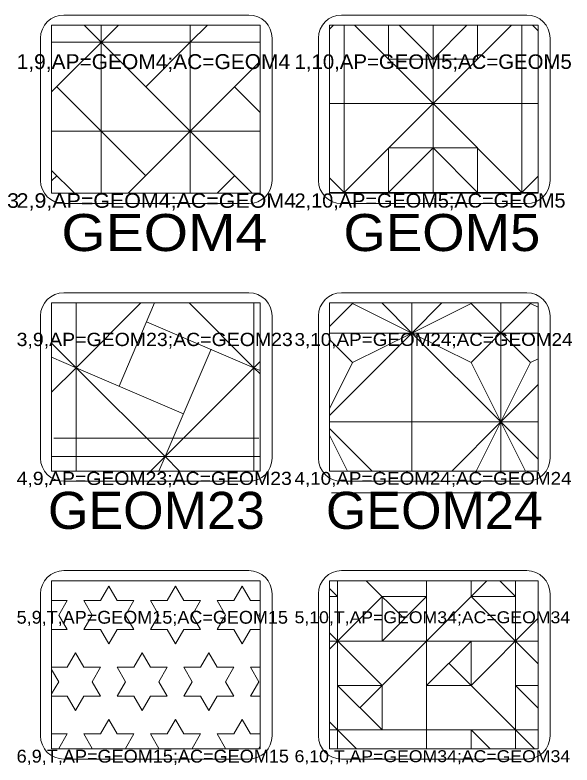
# Model space of a CAD drawing. Extents: x 95935 to 95946.4, y 95971.2 to 95974.7.
# Drawn here: x 95939.831 to 95941.033, y 95973.112 to 95974.732 of the extents above; entities that cross this region are included whole.
import ezdxf
from ezdxf.enums import TextEntityAlignment as Align

# ---------------------------------------------------------------- set-up
doc = ezdxf.new("R2010")
doc.units = 0
doc.header["$LTSCALE"] = 0.032
for name, color, linetype, lineweight in [('1', 7, 'Continuous', 13), ('2', 7, 'Continuous', 13), ('25', 7, 'Continuous', 13), ('6', 7, 'Continuous', 13), ('63', 7, 'Continuous', 13)]:
    doc.layers.add(name, color=color, linetype=linetype, lineweight=lineweight)
doc.layers.add('20', color=7, linetype='Continuous')

msp = doc.modelspace()

# ---------------------------------------------------------------- linework, layer by layer
at = {"layer": '1'}
for p, q in [((95939.9357, 95974.7318), (95940.3357, 95974.7318)), ((95940.5357, 95974.7318), (95940.9357, 95974.7318)), ((95939.8857, 95974.3747), (95939.8857, 95974.6818)), ((95940.3857, 95974.6818), (95940.3857, 95974.3747)), ((95940.4857, 95974.3747), (95940.4857, 95974.6818)), ((95940.9857, 95974.6818), (95940.9857, 95974.3747)), ((95940.3357, 95974.3247), (95939.9357, 95974.3247)), ((95940.9357, 95974.3247), (95940.5357, 95974.3247)), ((95939.9357, 95974.1318), (95940.3357, 95974.1318)), ((95940.5357, 95974.1318), (95940.9357, 95974.1318)), ((95939.8857, 95973.7747), (95939.8857, 95974.0818)), ((95940.3857, 95974.0818), (95940.3857, 95973.7747)), ((95940.4857, 95973.7747), (95940.4857, 95974.0818)), ((95940.9857, 95974.0818), (95940.9857, 95973.7747)), ((95940.3357, 95973.7247), (95939.9357, 95973.7247)), ((95940.9357, 95973.7247), (95940.5357, 95973.7247)), ((95939.9357, 95973.5318), (95940.3357, 95973.5318)), ((95940.5357, 95973.5318), (95940.9357, 95973.5318)), ((95939.8857, 95973.1747), (95939.8857, 95973.4818)), ((95940.3857, 95973.4818), (95940.3857, 95973.1747)), ((95940.4857, 95973.1747), (95940.4857, 95973.4818)), ((95940.9857, 95973.4818), (95940.9857, 95973.1747)), ((95940.3357, 95973.1247), (95939.9357, 95973.1247)), ((95940.9357, 95973.1247), (95940.5357, 95973.1247))]:
    msp.add_line(p, q, dxfattribs=at)
for centre, start, end in [((95939.9357, 95974.6818), 90, 180), ((95940.3357, 95974.6818), 0, 90), ((95940.5357, 95974.6818), 90, 180), ((95940.9357, 95974.6818), 0, 90), ((95939.9357, 95974.3747), 180, 270), ((95940.3357, 95974.3747), 270, 0), ((95940.5357, 95974.3747), 180, 270), ((95940.9357, 95974.3747), 270, 0), ((95939.9357, 95974.0818), 90, 180), ((95940.3357, 95974.0818), 0, 90), ((95940.5357, 95974.0818), 90, 180), ((95940.9357, 95974.0818), 0, 90), ((95939.9357, 95973.7747), 180, 270), ((95940.3357, 95973.7747), 270, 0), ((95940.5357, 95973.7747), 180, 270), ((95940.9357, 95973.7747), 270, 0), ((95939.9357, 95973.4818), 90, 180), ((95940.3357, 95973.4818), 0, 90), ((95940.5357, 95973.4818), 90, 180), ((95940.9357, 95973.4818), 0, 90), ((95939.9357, 95973.1747), 180, 270), ((95940.3357, 95973.1747), 270, 0), ((95940.5357, 95973.1747), 180, 270), ((95940.9357, 95973.1747), 270, 0)]:
    msp.add_arc(centre, 0.05, start, end, dxfattribs=at)
at = {"layer": '2'}
for points in [[(95940.3601, 95974.7099), (95939.9097, 95974.7099), (95939.9097, 95974.3468), (95940.3601, 95974.3468)], [(95940.9601, 95974.7099), (95940.5097, 95974.7099), (95940.5097, 95974.3468), (95940.9601, 95974.3468)], [(95940.3601, 95974.1099), (95939.9097, 95974.1099), (95939.9097, 95973.7468), (95940.3601, 95973.7468)], [(95940.9601, 95974.1099), (95940.5097, 95974.1099), (95940.5097, 95973.7468), (95940.9601, 95973.7468)], [(95940.3601, 95973.5099), (95939.9097, 95973.5099), (95939.9097, 95973.1468), (95940.3601, 95973.1468)], [(95940.9601, 95973.5099), (95940.5097, 95973.5099), (95940.5097, 95973.1468), (95940.9601, 95973.1468)]]:
    msp.add_lwpolyline(points, close=True, dxfattribs=at)
at = {"layer": '25'}
for p, q in [((95940.3569, 95973.8178), (95939.9141, 95973.8178)), ((95940.9569, 95973.6997), (95940.5141, 95973.6997))]:
    msp.add_line(p, q, dxfattribs=at)
at = {"layer": '6'}
for p, q in [((95939.9097, 95974.5657), (95940.0539, 95974.7099)), ((95940.2088, 95974.4808), (95939.9797, 95974.7099)), ((95940.0168, 95974.7099), (95940.0168, 95974.3468)), ((95940.2088, 95974.7099), (95940.2088, 95974.3468)), ((95940.2459, 95974.7099), (95940.2088, 95974.6728)), ((95940.5183, 95974.7099), (95940.5097, 95974.7013)), ((95940.541, 95974.7099), (95940.541, 95974.3468)), ((95940.733, 95974.5406), (95940.5637, 95974.7099)), ((95940.637, 95974.7099), (95940.637, 95974.6366)), ((95940.733, 95974.6366), (95940.6597, 95974.7099)), ((95940.733, 95974.7099), (95940.733, 95974.3468)), ((95940.9023, 95974.7099), (95940.733, 95974.5406)), ((95940.733, 95974.6366), (95940.8063, 95974.7099)), ((95940.829, 95974.7099), (95940.829, 95974.6366)), ((95940.925, 95974.7099), (95940.925, 95974.3468)), ((95940.9601, 95974.6975), (95940.9477, 95974.7099)), ((95939.9097, 95974.6728), (95940.3601, 95974.6728)), ((95940.1128, 95974.5768), (95940.2088, 95974.6728)), ((95940.2088, 95974.4808), (95940.3601, 95974.6321)), ((95940.637, 95974.6366), (95940.733, 95974.6366)), ((95940.829, 95974.6366), (95940.733, 95974.6366)), ((95939.9208, 95974.5768), (95940.0168, 95974.4808)), ((95940.3048, 95974.5768), (95940.3601, 95974.5215)), ((95940.5097, 95974.5406), (95940.9601, 95974.5406)), ((95940.541, 95974.3486), (95940.733, 95974.5406)), ((95940.733, 95974.5406), (95940.925, 95974.3486)), ((95939.9097, 95974.4808), (95940.3601, 95974.4808)), ((95940.1128, 95974.3848), (95940.0168, 95974.4808)), ((95940.0748, 95974.3468), (95940.2088, 95974.4808)), ((95940.3428, 95974.3468), (95940.2088, 95974.4808)), ((95939.9588, 95974.3468), (95939.9097, 95974.3959)), ((95939.9208, 95974.3848), (95939.9097, 95974.3737)), ((95940.3048, 95974.3848), (95940.2668, 95974.3468)), ((95940.5097, 95974.3799), (95940.541, 95974.3486)), ((95940.925, 95974.3486), (95940.9601, 95974.3837)), ((95940.5097, 95974.3486), (95940.9601, 95974.3486)), ((95940.541, 95974.3486), (95940.5392, 95974.3468)), ((95940.5428, 95974.3468), (95940.541, 95974.3486)), ((95940.637, 95974.3486), (95940.637, 95974.3468)), ((95940.6388, 95974.3468), (95940.637, 95974.3486)), ((95940.8272, 95974.3468), (95940.829, 95974.3486)), ((95940.829, 95974.3486), (95940.829, 95974.3468)), ((95940.925, 95974.3486), (95940.9232, 95974.3468)), ((95940.9268, 95974.3468), (95940.925, 95974.3486)), ((95939.9625, 95974.1099), (95939.9625, 95973.7468)), ((95940.1023, 95974.1099), (95939.9625, 95973.9701)), ((95940.1321, 95974.1099), (95940.0552, 95973.9304)), ((95940.3465, 95973.9701), (95940.2067, 95974.1099)), ((95940.3465, 95974.1099), (95940.3465, 95973.7468)), ((95940.5595, 95974.109), (95940.5097, 95974.0592)), ((95940.5595, 95974.109), (95940.5591, 95974.1099)), ((95940.6875, 95974.1099), (95940.6875, 95973.7468)), ((95940.7524, 95974.1099), (95940.6875, 95974.045)), ((95940.816, 95974.1099), (95940.8155, 95974.109)), ((95940.8155, 95974.109), (95940.9435, 95973.981)), ((95940.9435, 95974.109), (95940.8155, 95973.981)), ((95940.8795, 95974.1099), (95940.8795, 95973.7468)), ((95940.3465, 95973.9701), (95940.1148, 95974.0694)), ((95940.5097, 95974.045), (95940.9601, 95974.045)), ((95940.6875, 95974.045), (95940.8795, 95973.853)), ((95940.5097, 95974.0308), (95940.5595, 95973.981)), ((95940.1545, 95973.7781), (95940.2538, 95974.0098)), ((95939.9625, 95973.9701), (95939.9097, 95973.9927)), ((95940.5097, 95973.8814), (95940.5595, 95973.981)), ((95940.9435, 95973.981), (95940.9601, 95973.9893)), ((95939.9625, 95973.9701), (95940.1942, 95973.8708)), ((95940.3465, 95973.9701), (95940.3601, 95973.9643)), ((95940.8795, 95973.853), (95940.9601, 95973.9336)), ((95940.5097, 95973.853), (95940.9601, 95973.853)), ((95940.8795, 95973.853), (95940.7733, 95973.7468)), ((95940.9326, 95973.7468), (95940.8795, 95973.853)), ((95940.6017, 95973.7468), (95940.5097, 95973.8388)), ((95940.5486, 95973.7468), (95940.5097, 95973.8246)), ((95939.9097, 95973.7781), (95940.3601, 95973.7781)), ((95940.1545, 95973.7781), (95940.1232, 95973.7468)), ((95940.5271, 95973.5099), (95940.5271, 95973.1468)), ((95940.589, 95973.5099), (95940.6711, 95973.4278)), ((95940.7191, 95973.5099), (95940.7191, 95973.1468)), ((95940.7191, 95973.3798), (95940.8492, 95973.5099)), ((95940.8151, 95973.5099), (95940.8151, 95973.4758)), ((95940.9111, 95973.4758), (95940.877, 95973.5099)), ((95940.9111, 95973.5099), (95940.9111, 95973.1468)), ((95940.0329, 95973.4981), (95940.0149, 95973.467)), ((95940.0329, 95973.4981), (95940.0509, 95973.467)), ((95940.1769, 95973.4981), (95940.1589, 95973.467)), ((95940.1769, 95973.4981), (95940.1949, 95973.467)), ((95940.3209, 95973.4981), (95940.3029, 95973.467)), ((95940.3209, 95973.4981), (95940.3389, 95973.467)), ((95940.6231, 95973.4758), (95940.5097, 95973.3624)), ((95940.8151, 95973.4758), (95940.9111, 95973.4758)), ((95940.8151, 95973.4758), (95940.9601, 95973.3308)), ((95939.9429, 95973.467), (95939.9097, 95973.467)), ((95939.9429, 95973.467), (95939.9249, 95973.4358)), ((95939.9789, 95973.467), (95940.0149, 95973.467)), ((95939.9789, 95973.467), (95939.9969, 95973.4358)), ((95940.0869, 95973.467), (95940.0509, 95973.467)), ((95940.0869, 95973.467), (95940.0689, 95973.4358)), ((95940.1229, 95973.467), (95940.1589, 95973.467)), ((95940.1229, 95973.467), (95940.1409, 95973.4358)), ((95940.2309, 95973.467), (95940.1949, 95973.467)), ((95940.2309, 95973.467), (95940.2129, 95973.4358)), ((95940.2669, 95973.467), (95940.3029, 95973.467)), ((95940.2669, 95973.467), (95940.2849, 95973.4358)), ((95940.3601, 95973.467), (95940.3389, 95973.467)), ((95940.3601, 95973.4413), (95940.3569, 95973.4358)), ((95939.9429, 95973.4046), (95939.9249, 95973.4358)), ((95939.9789, 95973.4046), (95939.9969, 95973.4358)), ((95940.0869, 95973.4046), (95940.0689, 95973.4358)), ((95940.1229, 95973.4046), (95940.1409, 95973.4358)), ((95940.2309, 95973.4046), (95940.2129, 95973.4358)), ((95940.2669, 95973.4046), (95940.2849, 95973.4358)), ((95940.3601, 95973.4303), (95940.3569, 95973.4358)), ((95940.9601, 95973.4288), (95940.8151, 95973.2838)), ((95939.9429, 95973.4046), (95939.9097, 95973.4046)), ((95939.9789, 95973.4046), (95940.0149, 95973.4046)), ((95940.0329, 95973.3734), (95940.0149, 95973.4046)), ((95940.0329, 95973.3734), (95940.0509, 95973.4046)), ((95940.0869, 95973.4046), (95940.0509, 95973.4046)), ((95940.1229, 95973.4046), (95940.1589, 95973.4046)), ((95940.1769, 95973.3734), (95940.1589, 95973.4046)), ((95940.1769, 95973.3734), (95940.1949, 95973.4046)), ((95940.2309, 95973.4046), (95940.1949, 95973.4046)), ((95940.2669, 95973.4046), (95940.3029, 95973.4046)), ((95940.3209, 95973.3734), (95940.3029, 95973.4046)), ((95940.3209, 95973.3734), (95940.3389, 95973.4046)), ((95940.3601, 95973.4046), (95940.3389, 95973.4046)), ((95940.5097, 95973.3972), (95940.6231, 95973.2838)), ((95940.5097, 95973.3798), (95940.9601, 95973.3798)), ((95940.7191, 95973.3798), (95940.5751, 95973.2358)), ((95939.9609, 95973.3541), (95939.9429, 95973.323)), ((95939.9609, 95973.3541), (95939.9789, 95973.323)), ((95940.1049, 95973.3541), (95940.0869, 95973.323)), ((95940.1049, 95973.3541), (95940.1229, 95973.323)), ((95940.2489, 95973.3541), (95940.2309, 95973.323)), ((95940.2489, 95973.3541), (95940.2669, 95973.323)), ((95940.9111, 95973.1878), (95940.7671, 95973.3318)), ((95939.9097, 95973.323), (95939.9429, 95973.323)), ((95939.9097, 95973.3181), (95939.9249, 95973.2918)), ((95940.0149, 95973.323), (95939.9789, 95973.323)), ((95940.0149, 95973.323), (95939.9969, 95973.2918)), ((95940.0509, 95973.323), (95940.0869, 95973.323)), ((95940.0509, 95973.323), (95940.0689, 95973.2918)), ((95940.1589, 95973.323), (95940.1229, 95973.323)), ((95940.1589, 95973.323), (95940.1409, 95973.2918)), ((95940.1949, 95973.323), (95940.2309, 95973.323)), ((95940.1949, 95973.323), (95940.2129, 95973.2918)), ((95940.3029, 95973.323), (95940.2669, 95973.323)), ((95940.3029, 95973.323), (95940.2849, 95973.2918)), ((95940.3389, 95973.323), (95940.3569, 95973.2918)), ((95940.3389, 95973.323), (95940.3601, 95973.323)), ((95939.9097, 95973.2655), (95939.9249, 95973.2918)), ((95940.0149, 95973.2606), (95939.9969, 95973.2918)), ((95940.0509, 95973.2606), (95940.0689, 95973.2918)), ((95940.1589, 95973.2606), (95940.1409, 95973.2918)), ((95940.1949, 95973.2606), (95940.2129, 95973.2918)), ((95940.3029, 95973.2606), (95940.2849, 95973.2918)), ((95940.3389, 95973.2606), (95940.3569, 95973.2918)), ((95939.9097, 95973.2606), (95939.9429, 95973.2606)), ((95939.9609, 95973.2294), (95939.9429, 95973.2606)), ((95939.9609, 95973.2294), (95939.9789, 95973.2606)), ((95940.0149, 95973.2606), (95939.9789, 95973.2606)), ((95940.0509, 95973.2606), (95940.0869, 95973.2606)), ((95940.1049, 95973.2294), (95940.0869, 95973.2606)), ((95940.1049, 95973.2294), (95940.1229, 95973.2606)), ((95940.1589, 95973.2606), (95940.1229, 95973.2606)), ((95940.1949, 95973.2606), (95940.2309, 95973.2606)), ((95940.2489, 95973.2294), (95940.2309, 95973.2606)), ((95940.2489, 95973.2294), (95940.2669, 95973.2606)), ((95940.3029, 95973.2606), (95940.2669, 95973.2606)), ((95940.3389, 95973.2606), (95940.3601, 95973.2606)), ((95940.9601, 95973.2368), (95940.9591, 95973.2358)), ((95940.0329, 95973.2101), (95940.0149, 95973.179)), ((95940.0329, 95973.2101), (95940.0509, 95973.179)), ((95940.1769, 95973.2101), (95940.1589, 95973.179)), ((95940.1769, 95973.2101), (95940.1949, 95973.179)), ((95940.3209, 95973.2101), (95940.3029, 95973.179)), ((95940.3209, 95973.2101), (95940.3389, 95973.179)), ((95940.5271, 95973.1878), (95940.5097, 95973.2052)), ((95940.5097, 95973.1878), (95940.9601, 95973.1878)), ((95940.5271, 95973.1878), (95940.5681, 95973.1468)), ((95940.9111, 95973.1878), (95940.9521, 95973.1468)), ((95939.9429, 95973.179), (95939.9097, 95973.179)), ((95939.9429, 95973.179), (95939.9249, 95973.1478)), ((95939.9789, 95973.179), (95940.0149, 95973.179)), ((95939.9789, 95973.179), (95939.9969, 95973.1478)), ((95940.0869, 95973.179), (95940.0509, 95973.179)), ((95940.0869, 95973.179), (95940.0689, 95973.1478)), ((95940.1229, 95973.179), (95940.1589, 95973.179)), ((95940.1229, 95973.179), (95940.1409, 95973.1478)), ((95940.2309, 95973.179), (95940.1949, 95973.179)), ((95940.2309, 95973.179), (95940.2129, 95973.1478)), ((95940.2669, 95973.179), (95940.3029, 95973.179)), ((95940.2669, 95973.179), (95940.2849, 95973.1478)), ((95940.3601, 95973.179), (95940.3389, 95973.179)), ((95939.9255, 95973.1468), (95939.9249, 95973.1478)), ((95939.9963, 95973.1468), (95939.9969, 95973.1478)), ((95940.0695, 95973.1468), (95940.0689, 95973.1478)), ((95940.1403, 95973.1468), (95940.1409, 95973.1478)), ((95940.2135, 95973.1468), (95940.2129, 95973.1478)), ((95940.2843, 95973.1468), (95940.2849, 95973.1478)), ((95940.3601, 95973.1533), (95940.3569, 95973.1478)), ((95940.3575, 95973.1468), (95940.3569, 95973.1478))]:
    msp.add_line(p, q, dxfattribs=at)
for points in [[(95940.637, 95974.3486), (95940.733, 95974.4446), (95940.637, 95974.4446)], [(95940.733, 95974.4446), (95940.829, 95974.3486), (95940.829, 95974.4446)], [(95940.6231, 95973.4758), (95940.6231, 95973.3798), (95940.7191, 95973.4758)], [(95940.8151, 95973.2838), (95940.8151, 95973.3798), (95940.7191, 95973.2838)], [(95940.6231, 95973.2838), (95940.5271, 95973.2838), (95940.6231, 95973.1878)]]:
    msp.add_lwpolyline(points, close=True, dxfattribs=at)
for points in [[(95940.5097, 95973.8672), (95940.6875, 95974.045), (95940.6226, 95974.1099)], [(95940.5595, 95973.981), (95940.6875, 95974.045), (95940.5595, 95974.109)], [(95940.8155, 95974.109), (95940.6875, 95974.045), (95940.8155, 95973.981), (95940.8795, 95973.853), (95940.9435, 95973.981)], [(95940.9601, 95974.1007), (95940.9435, 95974.109), (95940.9431, 95974.1099)], [(95939.9097, 95973.9173), (95939.9625, 95973.9701), (95939.9097, 95974.0229)], [(95940.3601, 95973.9837), (95940.3465, 95973.9701), (95940.3601, 95973.9565)], [(95939.9625, 95973.9701), (95940.1545, 95973.7781), (95940.3465, 95973.9701)], [(95940.9601, 95973.7724), (95940.8795, 95973.853), (95940.8264, 95973.7468)], [(95940.1858, 95973.7468), (95940.1545, 95973.7781), (95940.1411, 95973.7468)], [(95940.5097, 95973.4758), (95940.5271, 95973.4758), (95940.5097, 95973.4932)], [(95940.9601, 95973.2838), (95940.9111, 95973.2838), (95940.9601, 95973.2348)], [(95940.8561, 95973.1468), (95940.8151, 95973.1878), (95940.8151, 95973.1468)]]:
    msp.add_lwpolyline(points, dxfattribs=at)

# ---------------------------------------------------------------- texts
at = {"layer": '20'}
for s, width, p in [(' GEOM4', 1.15, (95940.1358, 95974.222)), (' GEOM5', 1.1, (95940.7358, 95974.222)), ('GEOM23', 1.05, (95940.1358, 95973.622)), ('GEOM24', 1.05, (95940.7358, 95973.622))]:
    msp.add_text(s, height=0.08, dxfattribs=dict(at, width=width)).set_placement(p, align=Align.CENTER)
at = {"layer": '63'}
for s, height, width, p in [('1,9,AP=GEOM4;AC=GEOM4', 0.0322, 1.05, (95939.8341, 95974.615)), ('1,10,AP=GEOM5;AC=GEOM5', 0.0313, 1.05, (95940.4341, 95974.6154)), ('2,8,AP=GEOM3;AC=GEOM3', 0.0315, 1.1, (95939.2341, 95974.3153)), ('2,9,AP=GEOM4;AC=GEOM4', 0.0314, 1.1, (95939.8341, 95974.3154)), ('2,10,AP=GEOM5;AC=GEOM5', 0.0306, 1.05, (95940.4341, 95974.3158)), ('3,9,AP=GEOM23;AC=GEOM23', 0.0286, 1.1, (95939.8341, 95974.0168)), ('3,10,AP=GEOM24;AC=GEOM24', 0.0277, 1.1, (95940.4341, 95974.0172)), ('4,9,AP=GEOM23;AC=GEOM23', 0.0285, 1.1, (95939.8341, 95973.7168)), ('4,10,AP=GEOM24;AC=GEOM24', 0.0276, 1.1, (95940.4341, 95973.7173)), ('5,9,T,AP=GEOM15;AC=GEOM15', 0.0277, 1.05, (95939.8341, 95973.4172)), ('5,10,T,AP=GEOM34;AC=GEOM34', 0.0259, 1.1, (95940.4341, 95973.4181)), ('6,9,T,AP=GEOM15;AC=GEOM15', 0.0278, 1.05, (95939.8341, 95973.1172)), ('6,10,T,AP=GEOM34;AC=GEOM34', 0.0259, 1.1, (95940.4341, 95973.1181))]:
    msp.add_text(s, height=height, dxfattribs=dict(at, width=width)).set_placement(p)

doc.saveas('drawing.dxf')
